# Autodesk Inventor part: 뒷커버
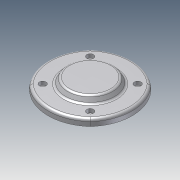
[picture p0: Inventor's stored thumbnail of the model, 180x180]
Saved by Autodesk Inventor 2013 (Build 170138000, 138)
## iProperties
Company: 한국ATC센터
Created: 2014-08
Part Number: 뒷커버
Document SubType Name: Modeling
Designer: KYOUNG IL JANG
Density: 1 g/cm^3
Material: 일반
Mass: 95.9791 g
Surface Area: 228.85 cm^2
Volume: 95.9791 cm^3
Author: KYOUNG IL JANG
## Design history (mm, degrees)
sketch "스케치1"
  geometry: C1 r 30 at (0, 0) reference; A1 r 53.623 centre (0, -3.623) between (36.062, 36.062) and (-36.062, 36.062) reference; A2 r 53.623 centre (3.623, 0) between (-36.062, 36.062) and (-36.062, -36.062) reference; A3 r 53.623 centre (-3.623, 0) between (36.062, -36.062) and (36.062, 36.062) reference; A4 r 53.623 centre (0, 3.623) between (-36.062, -36.062) and (36.062, -36.062) reference; 1 further point
  node "참조9"
  node "참조14"
  node "참조15"
  node "참조16"
  node "참조17"
extrude "돌출1" new body sketch "스케치1" distance "d0" = 8; taper "d1" = 0 deg
sketch "스케치2"
  geometry: C1 r 30 at (0, 0); 1 further point
  constraints: 1 centre point, 1 coincident
  dimensions: "d2" = 60 diameter of C1
extrude "돌출2" join sketch "스케치2" distance "d3" = 7; taper "d4" = -30 deg
sketch "스케치3"
  geometry: C1 r 1.621 at (28.284, 28.284) reference; C2 r 1.621 at (-28.284, 28.284) reference; C3 r 1.621 at (-28.284, -28.284) reference; C4 r 1.621 at (28.284, -28.284) reference; 1 further point
hole "구멍2" sketch "스케치3" at (-28.284, -28.284), (-28.284, 28.284), (28.284, 28.284), (28.284, -28.284) diameter "d14" = 4.5; stored, may be unused: countersink angle "d18" = 90 deg, drill point angle "d20" = 118 deg; dims "d15" = 6, "d16" = 8, "d17" = 4.4, "d19" = 20
extrude "돌출3" join sketch "스케치1" distance "d21" = 12; taper "d22" = 0 deg
hole "구멍3" diameter "d25" = 30; stored, may be unused: countersink angle "d29" = 90 deg, drill point angle "d31" = 0 deg; dims "d23" = 10, "d24" = 10, "d26" = 6, "d27" = 40, "d28" = 12, "d30" = 15
fillet "모깎기1" dims "d32" = 3, "d33" = 0.3
chamfer "모따기1" distance "d34" = 1; stored, may be unused: second distance "d35" = 2, angle "d36" = 45 deg
node "솔리드1"
node "참조18"
node "참조19"
node "참조20"
node "참조21"
